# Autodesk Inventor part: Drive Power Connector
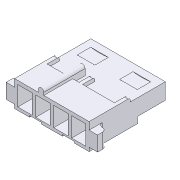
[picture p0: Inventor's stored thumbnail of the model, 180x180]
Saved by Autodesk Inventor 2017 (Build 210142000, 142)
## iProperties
Created: 2016-11
Part Number: Drive Power Connector
Material: Generic
Document SubType Name: Modeling
Designer: DanielSeverino
Density: 1 g/cm^3
Appearance: Default
Company: Autodesk Inc.
Sending System: Autodesk Inventor 2017
Preprocessor: ST-DEVELOPER v16.5
GlobalPropertyList: <PropertyList/>
Title: C:\Users\DanielSeverino\Desktop\Drive Power Connector.stp
Author: DanielSeverino
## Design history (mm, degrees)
feature "Solid1"
body "Solid2"
